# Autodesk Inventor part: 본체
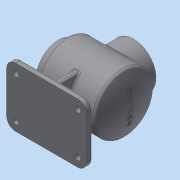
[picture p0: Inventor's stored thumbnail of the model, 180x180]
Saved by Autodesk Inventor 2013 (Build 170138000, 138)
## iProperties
Created: 2016-09
Part Number: 본체
Material: 일반
Document SubType Name: Modeling
Designer: dgall
Density: 1 g/cm^3
Author: dgall
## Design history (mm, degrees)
sketch "스케치1"
  geometry: L1 (-61.831, 0)-(60.169, 0); L2 (-61.831, 27)-(-46.831, 27); L3 (-46.831, 27)-(-46.831, 47); L4 (-46.831, 47)-(46.831, 47); L5 (-61.831, 27)-(-61.831, 38); L6 (-61.831, 38)-(-49.831, 38); L7 (-49.831, 38)-(-49.831, 50); L8 (-49.831, 50)-(48.731, 50); A1 r 115 centre (-54.831, 0) between (60.169, 0) and (48.731, 50); A2 r 112 centre (-54.831, 0) between (57.169, 0) and (46.831, 47); 2 further points
  constraints: 16 end point, 4 parallel, 4 point on circle, 3 perpendicular, 2 centre point, 2 horizontal alignment, 2 vertical alignment, 1 coincident, 1 horizontal, 1 midpoint, 1 point on line
  dimensions: "d2" = 115 radius of A1; "d3" = 12 distance of L5.end L6.end; "d4" = 3 distance between parallel lines of L8 L4; "d5" = 110 distance from line of L1.end L7; "d6" = 3 distance of L1.end A2.start; "d7" = 27 distance between parallel lines of L1 L2; "d8" = 38 distance between parallel lines of L1 L6; "d9" = 50 distance between parallel lines of L1 L8; "d10" = 15 distance of L2.start L2.end
revolve "회전1" sketch "스케치1" stored, may be unused: angle "d11" = 90 deg
node "작업 평면2"
sketch "스케치2"
  geometry: L1 (67.5, -50)-(-67.5, -50); L2 (-67.5, -50)-(-67.5, 50); L3 (-67.5, 50)-(67.5, 50); L4 (67.5, 50)-(67.5, -50); L5 (-48.731, 50)-(-48.731, -50) reference; L6 (49.831, 50)-(49.831, -50) reference; L7 (49.831, -50)-(-48.731, -50) reference; A1 r 115 centre (54.831, 0) between (-48.731, 50) and (-48.731, -50) reference; 1 further point
  constraints: 8 end point, 2 parallel, 1 horizontal, 1 perpendicular
  dimensions: "d13" = 135 distance of L1.start L1.end; "d15" = 100 distance of L1.end L2.end; "d95" = 67.5 distance from line of L4 point (0, 0); "d96" = 50 distance from line of L3 point (0, 0)
extrude "돌출1" join sketch "스케치2" distance "d16" = 10; taper "d17" = 0 deg
node "작업 평면3"
sketch "스케치3"
  geometry: L1 (0, 0)-(0, 10) reference; L2 (0, 10)-(100, 10) reference; L3 (100, 10)-(100, 0) reference; L4 (100, 0)-(0, 0) reference; L5 (90, 10)-(90, 52); L6 (10, 10)-(10, 52); C1 r 47 at (50, 82) reference; A1 r 50 centre (50, 82) between (90, 52) and (10, 52) reference; 1 further point
  constraints: 4 end point, 2 point on circle, 2 point on line, 1 parallel, 1 perpendicular
  dimensions: "d19" = 80 distance between parallel lines of L5 L6; "d20" = 40 distance from line of point (50, 82) L6
extrude "돌출2" join sketch "스케치3" stored distance "d21" = 10; taper "d22" = 0 deg
feature "리브1" dims "d30" = 1, "d31" = 10, "d32" = 0, "d33" = 0, "d34" = 1, "d35" = 1
feature "리브2" dims "d36" = 1, "d37" = 10, "d38" = 0, "d39" = 0, "d40" = 1, "d41" = 1
node "작업 평면4"
sketch "스케치5"
  geometry: L1 (49.831, 50)-(49.831, -50) reference; C1 r 38 at (-0.169, 0); 1 further point
  constraints: 1 centre point, 1 horizontal alignment
  dimensions: "d100" = 76 diameter of C1; "d101" = 50 distance from line of L1 C1.centre
extrude "돌출3" join sketch "스케치5" stored distance "d44" = 10; taper "d45" = 0 deg
sketch "스케치11"
  geometry: C1 r 38 at (0, 0) reference; C2 r 27 at (0, 0); 1 further point
  constraints: 1 centre point, 1 concentric
  dimensions: "d122" = 54 diameter of C2
extrude "돌출5" cut sketch "스케치11" stored distance "d105" = 10; taper "d106" = 0 deg
sketch "스케치12"
  geometry: C1 r 27 at (0, 0) reference; 1 further point
  constraints: 1 vertical alignment
  dimensions: "d123" = 32.5 distance of C1.centre point (0, 32.5)
hole "구멍4" sketch "스케치12" at (0, 32.5) diameter "d108" = 3.242; stored, may be unused: countersink angle "d112" = 90 deg, drill point angle "d114" = 118 deg; dims "d109" = 8, "d110" = 4, "d111" = 2, "d113" = 10
fillet "모깎기8" dims "d121" = 3
sketch "스케치8"
  geometry: C1 r 38 at (0, 0) reference; 1 further point
  constraints: 1 vertical alignment
  dimensions: "d61" = 32.5 distance of C1.centre point (0, 32.5)
hole "구멍2" sketch "스케치8" at (0, 32.5) diameter "d62" = 3.242; stored, may be unused: countersink angle "d66" = 90 deg, drill point angle "d68" = 118 deg; dims "d63" = 8, "d64" = 4, "d65" = 2, "d67" = 10
fillet "모깎기1" dims "d72" = 5
fillet "모깎기2" dims "d73" = 2
fillet "모깎기3" dims "d74" = 3
fillet "모깎기4" dims "d75" = 3
fillet "모깎기5" dims "d76" = 15
fillet "모깎기6" dims "d77" = 3
sketch "스케치9"
  geometry: L1 (-36.726, -8)-(-8, -8) reference; L2 (-8, -8)-(-8, -37) reference; L3 (-2, -43)-(2, -43) reference; L4 (8, -37)-(8, -8) reference; L5 (8, -8)-(36.726, -8) reference; L6 (42.749, -2)-(42.749, 2) reference; L7 (36.726, 8)-(8, 8) reference; L8 (8, 8)-(8, 37) reference; L9 (2, 43)-(-2, 43) reference; L10 (-8, 37)-(-8, 8) reference; L11 (-8, 8)-(-36.726, 8) reference; L12 (-42.749, 2)-(-42.749, -2) reference; L13 (-52.5, -47)-(52.5, -47) reference; L14 (64.5, -35)-(64.5, 35) reference; L15 (52.5, 47)-(-52.5, 47) reference; L16 (-64.5, 35)-(-64.5, -35) reference; A1 r 6 centre (-2, -37) between (-8, -37) and (-2, -43) reference; A2 r 6 centre (2, -37) between (2, -43) and (8, -37) reference; A3 r 6 centre (2, 37) between (8, 37) and (2, 43) reference; A4 r 6 centre (-2, 37) between (-2, 43) and (-8, 37) reference; A5 r 15 centre (-52.5, 35) between (-52.5, 50) and (-67.5, 35) reference; A6 r 12 centre (52.5, -35) between (52.5, -47) and (64.5, -35) reference; A7 r 12 centre (52.5, 35) between (64.5, 35) and (52.5, 47) reference; A8 r 12 centre (-52.5, 35) between (-52.5, 47) and (-64.5, 35) reference; A9 r 12 centre (-52.5, -35) between (-64.5, -35) and (-52.5, -47) reference; 5 further points
  constraints: 1 coincident, 4 other
hole "구멍3" sketch "스케치9" diameter "d81" = 10; stored, may be unused: countersink angle "d85" = 90 deg, drill point angle "d87" = 118 deg; dims "d82" = 8, "d83" = 4, "d84" = 2, "d86" = 10
node "작업 평면5"
sketch "스케치10"
  geometry: C1 r 50 at (0, 0) reference; C2 r 47.045 at (0, 0) reference; 2 further points
  constraints: 1 coincident, 1 other
feature "엠보싱1" sketch "스케치10" dims "d89" = 0.5, "d90" = 0
chamfer "모따기1" distance "d91" = 1; stored, may be unused: second distance "d92" = 2, angle "d93" = 45 deg
fillet "모깎기7" dims "d94" = 3
chamfer "모따기3" distance "d124" = 1; stored, may be unused: second distance "d125" = 2, angle "d126" = 45 deg
node "솔리드1"
sketch "스케치4"
  geometry: L1 (46.831, 47)-(-46.831, 47) reference; L2 (-46.831, 47)-(-46.831, 27) reference; L3 (-46.831, 27)-(-61.831, 27) reference; L4 (-61.831, 27)-(-61.831, 38) reference; L5 (-61.831, 38)-(-49.831, 38) reference; L6 (-49.831, 38)-(-49.831, 50) reference; L7 (-49.831, 50)-(48.731, 50) reference; L8 (48.731, -50)-(5, -50) reference; L9 (5, -50)-(5, -72) reference; L10 (5, -72)-(67.5, -72) reference; L11 (67.5, -72)-(67.5, -82) reference; L12 (67.5, -82)-(-67.5, -82) reference; L13 (-67.5, -82)-(-67.5, -72) reference; L14 (-67.5, -72)-(-5, -72) reference; L15 (-5, -72)-(-5, -50) reference; L16 (-5, -50)-(-49.831, -50) reference; L17 (-49.831, -50)-(-49.831, -38) reference; L18 (-49.831, -38)-(-61.831, -38) reference; L19 (-61.831, -38)-(-61.831, -27) reference; L20 (-61.831, -27)-(-46.831, -27) reference; L21 (-46.831, -27)-(-46.831, -47) reference; L22 (-46.831, -47)-(46.831, -47) reference; L23 (-40, -72)-(-38.075, -50); L24 (40, -72)-(38.077, -50.023); L25 (46.831, 47)-(-46.831, 47) reference; L26 (-46.831, 47)-(-46.831, 27) reference; L27 (-46.831, 27)-(-61.831, 27) reference; L28 (-61.831, 27)-(-61.831, 38) reference; L29 (-61.831, 38)-(-49.831, 38) reference; L30 (-49.831, 38)-(-49.831, 50) reference; L31 (-49.831, 50)-(48.731, 50) reference; L32 (48.731, -50)-(5, -50) reference; L33 (5, -50)-(5, -72) reference; L34 (5, -72)-(67.5, -72) reference; L35 (67.5, -72)-(67.5, -82) reference; L36 (67.5, -82)-(-67.5, -82) reference; L37 (-67.5, -82)-(-67.5, -72) reference; L38 (-67.5, -72)-(-5, -72) reference; L39 (-5, -72)-(-5, -50) reference; L40 (-5, -50)-(-49.831, -50) reference; L41 (-49.831, -50)-(-49.831, -38) reference; L42 (-49.831, -38)-(-61.831, -38) reference; L43 (-61.831, -38)-(-61.831, -27) reference; L44 (-61.831, -27)-(-46.831, -27) reference; L45 (-46.831, -27)-(-46.831, -47) reference; L46 (-46.831, -47)-(46.831, -47) reference; A1 r 112 centre (-54.831, 0) between (46.831, -47) and (46.831, 47) reference; A2 r 115 centre (-54.831, 0) between (48.731, -50) and (48.731, 50) reference; A3 r 112 centre (-54.831, 0) between (46.831, -47) and (46.831, 47) reference; A4 r 115 centre (-54.831, 0) between (48.731, -50) and (48.731, 50) reference; 1 further point
  constraints: 4 end point, 3 point on line
  dimensions: "d24" = 95 deg angle of L14 L23; "d97" = 40 horizontal distance of point (0, 0) L23.start; "d98" = 40 horizontal distance of L24.start point (0, 0); "d99" = 95 deg angle of L10 L24
pattern_circular "원형 패턴3" dims angle "d116" = 360 deg
pattern_circular "원형 패턴2" dims angle "d70" = 360 deg
node "투영된 루프1"
node "투영된 루프2"
node "절단 모서리 투영1"
node "절단 모서리 투영2"
node "절단 모서리 투영3"
node "절단 모서리 투영4"
other parameters: "d12" = -82, "d18" = -67.5, "d42" = -147
